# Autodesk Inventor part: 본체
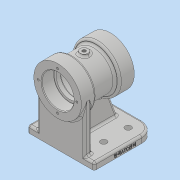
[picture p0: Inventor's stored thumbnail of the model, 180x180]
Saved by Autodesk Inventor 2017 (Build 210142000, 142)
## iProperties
Part Number: 본체
Material: 일반
Document SubType Name: Modeling
Designer: mrc
Density: 1 g/cm^3
Appearance: 기본값
Author: mrc
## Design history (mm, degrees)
sketch "스케치2"
  geometry: L1 (0, 35)-(-22, 35); L2 (-22, 35)-(-22, 28.5); L3 (-22, 28.5)-(-56, 28.5); L4 (-56, 28.5)-(-56, 35); L5 (-56, 35)-(-78, 35); L6 (-78, 35)-(-78, 23.5); L7 (-78, 23.5)-(-60, 23.5); L8 (-60, 23.5)-(-60, 20); L9 (-60, 20)-(-54, 20); L10 (-54, 20)-(-54, 23); L11 (-54, 23)-(-24, 23); L12 (-24, 23)-(-24, 20); L13 (-24, 20)-(-18, 20); L14 (-18, 20)-(-18, 23.5); L15 (-18, 23.5)-(0, 23.5); L16 (0, 35)-(0, 23.5); L17 (0, 0)-(-45.758, 0)
  constraints: 34 end point, 10 perpendicular, 4 horizontal, 2 point on line, 2 vertical, 1 vertical alignment
  dimensions: "d3" = 47 diameter of L15 L17; "d4" = 40 diameter of L13 L17; "d5" = 46 diameter of L11 L17; "d6" = 40 diameter of L9 L17; "d7" = 47 diameter of L7 L17; "d8" = 70 diameter of L1 L17; "d9" = 57 diameter of L3 L17; "d11" = 18 distance of L14.end L15.end; "d12" = 6 distance of L12.end L13.end; "d13" = 18 distance of L6.end L7.end; "d14" = 6 distance of L8.end L9.end; "d15" = 30 distance of L10.end L11.end; "d16" = 22 distance of L1.start L1.end; "d17" = 22 distance of L4.end L5.end
revolve "회전1" sketch "스케치2" stored, may be unused: angle "d18" = 90 deg
sketch "스케치3" dims "d19" = 57
  geometry: 3 further points
  constraints: 2 vertical alignment, 1 coincident, 2 other
hole "구멍1" sketch "스케치3" at (0, 28.5) diameter "d20" = 3.242; stored, may be unused: countersink angle "d24" = 90 deg, drill point angle "d26" = 118 deg; dims "d21" = 10, "d22" = 4, "d23" = 2, "d25" = 12
node "작업 평면2"
sketch "스케치4"
  geometry: L1 (0, -35)-(0, 35) reference; C1 r 6 at (-39, 0); 2 further points
  constraints: 1 centre point, 1 horizontal alignment, 1 midpoint
  dimensions: "d32" = 12 diameter of C1; "d33" = 39 distance from line of C1.centre L1
extrude "돌출2" join sketch "스케치4" stored distance "d34" = 20; taper "d35" = 0 deg
hole "구멍2" diameter "d38" = 5.188; stored, may be unused: countersink angle "d42" = 90 deg, drill point angle "d44" = 0 deg; dims "d36" = 10, "d37" = 10, "d39" = 12, "d40" = 4, "d41" = 2, "d43" = 16
node "작업 평면3"
sketch "스케치5"
  geometry: L1 (5, -49)-(95, -49); L2 (95, -49)-(95, 49); L3 (95, 49)-(5, 49); L4 (5, -49)-(5, 49); L5 (0, 35)-(0, -35) reference; 2 further points
  constraints: 8 end point, 2 perpendicular, 1 coincident, 1 horizontal, 1 parallel
  dimensions: "d47" = 98 distance of L1.end L2.end; "d83" = 49 distance from line of point (0, 0) L1; "d84" = 90 distance of L1.start L1.end; "d85" = 5 distance between parallel lines of L5 L4
extrude "돌출3" join sketch "스케치5" distance "d48" = 10; taper "d49" = 0 deg
fillet "모깎기1" dims "d50" = 20
node "작업 평면4"
sketch "스케치6"
  geometry: L1 (0, 35)-(72, 35); L2 (72, 35)-(72, -35); L3 (72, -35)-(0, -35); C1 r 35 at (0, 0) reference; A1 r 35 centre (0, 0) between (0, 35) and (0, -35) reference; A2 r 35 centre (0, 0) between (0, -35) and (0, 35); 1 further point
  constraints: 6 end point, 4 point on circle, 2 horizontal, 2 tangent, 1 centre point, 1 coincident, 1 vertical
  dimensions: "d52" = 72 distance from line of L2 point (0, 0)
extrude "돌출6" join sketch "스케치6" distance "d74" = 10; taper "d75" = 0 deg
sketch "스케치7"
  geometry: L1 (-71.927, -39.577)-(-83, -70); L2 (-95, -70)-(-75, -70) reference; L3 (-75, -70)-(-5, -70) reference; 1 further point
  constraints: 2 end point, 1 point on line
  dimensions: "d55" = 70 deg angle of L3 L1; "d56" = 12 distance of L2.start L1.end
feature "리브1" sketch "스케치7" dims "d57" = 1, "d58" = 10, "d59" = 0, "d60" = 0, "d61" = 1, "d62" = 1
sketch "스케치8"
  geometry: L1 (-5, -49)-(-5, 49) reference; C1 r 4.5 at (-39, -29); C2 r 4.5 at (-75, -29); C3 r 4.5 at (-39, 29); C4 r 4.5 at (-75, 29); 1 further point
  constraints: 4 centre point, 2 vertical alignment, 1 horizontal alignment
  dimensions: "d63" = 9 diameter of C1; "d64" = 9 diameter of C2; "d65" = 36 distance of C2.centre C1.centre; "d67" = 9 diameter of C3; "d68" = 9 diameter of C4; "d69" = 36 distance of C4.centre C3.centre; "d70" = 58 distance of C4.centre C2.centre; "d71" = 29 vertical distance of C1.centre point (0, 0); "d86" = 70 distance from line of C2.centre L1
extrude "돌출5" cut sketch "스케치8" distance "d72" = 10; taper "d73" = 0 deg
node "작업 평면5"
fillet "모깎기2" dims "d76" = 0.3, "d77" = 3
chamfer "모따기1" distance "d78" = 1; stored, may be unused: second distance "d79" = 2, angle "d80" = 45 deg
fillet "모깎기3" dims "d81" = 3
fillet "모깎기5" dims "d87" = 3
fillet "모깎기6" dims "d88" = 3
sketch "스케치9"
  geometry: L1 (0, 0)-(67, 0) reference; L2 (-3, 7)-(-3, 0) reference; 2 further points
  constraints: 1 other
  dimensions: "d89" = 4 distance from line of L1 point (42, 4); "d90" = 45 distance from line of point (42, 4) L2
feature "엠보싱1" sketch "스케치9" dims "d91" = 0.5, "d92" = 0
node "솔리드2"
pattern_circular "원형 패턴1" dims angle "d28" = 360 deg
mirror "미러2"
other parameters: "d31" = 31.5, "d51" = -5, "d93" = -39
